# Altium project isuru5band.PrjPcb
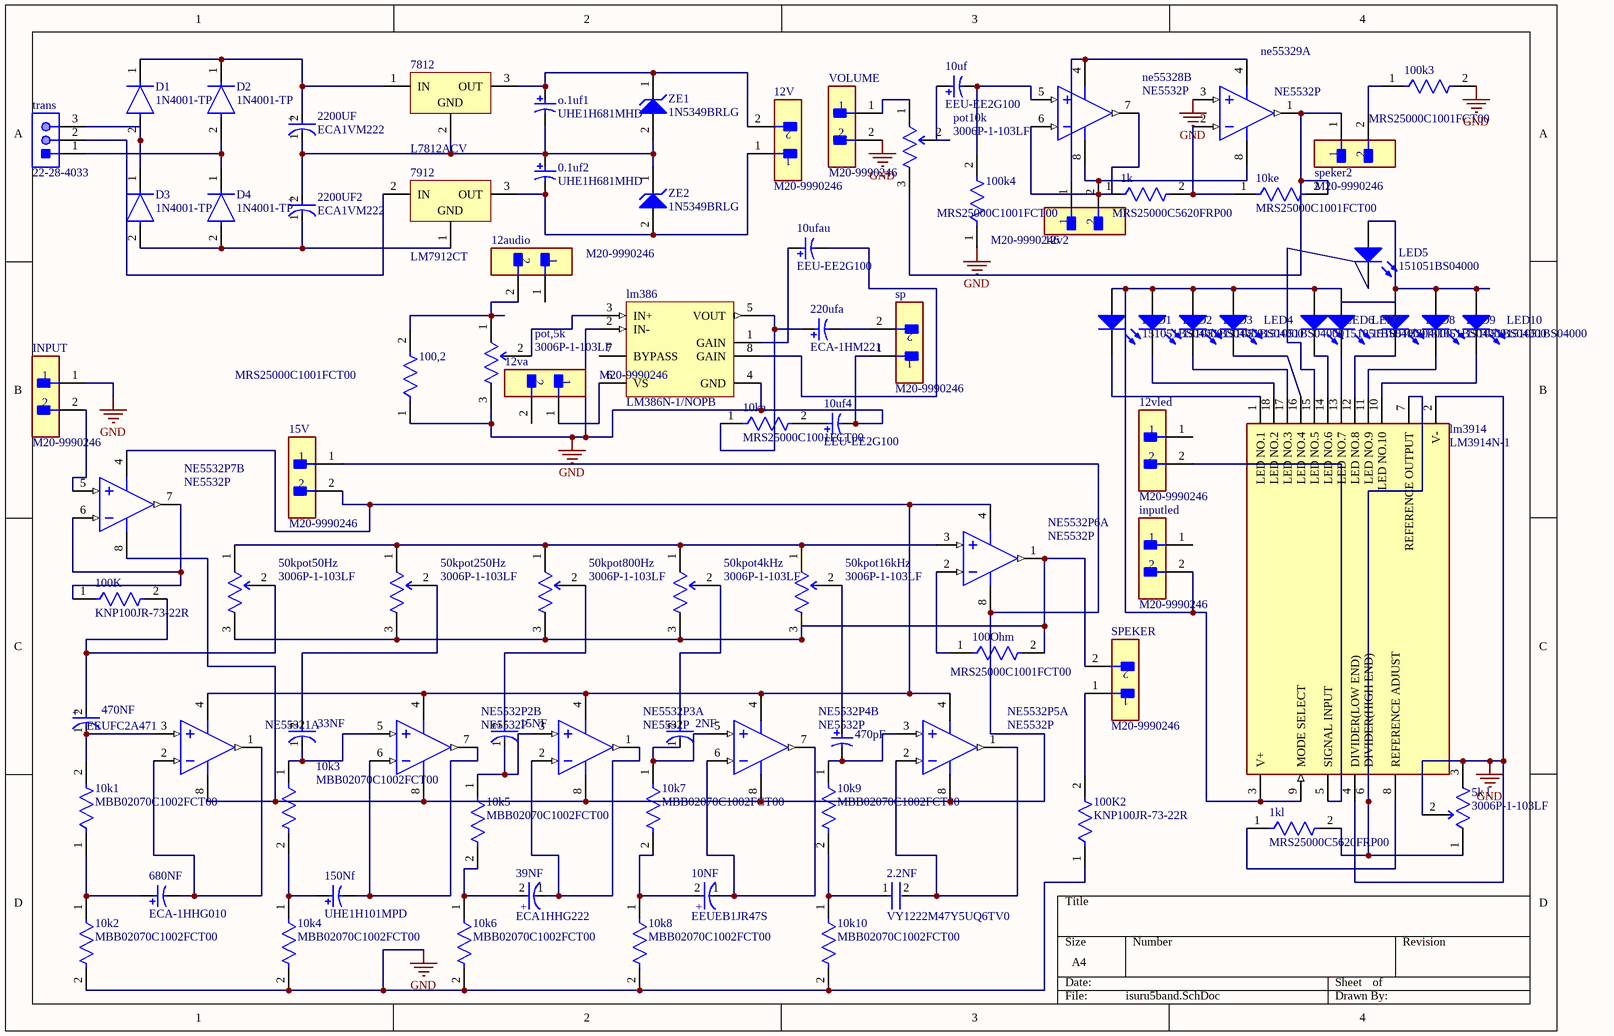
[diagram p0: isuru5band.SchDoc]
1 sheet, 88 parts. Net scope: global (net labels, ports and power ports of the same name join across sheets).
Board file: isuru5bandpcb.PcbDoc

## Sheet isuru5band.SchDoc
size A4; SheetNumber: 1; SheetTotal: 1

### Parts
0.1uf2  UHE1H681MHD  [NIC-UHE-12.5x31.5-2_V]
1k  MRS25000C5620FRP00  [FP-MRS25-MFG]
1kl  MRS25000C5620FRP00  [FP-MRS25-MFG]
2.2NF  VY1222M47Y5UQ6TV0  [FP-VY1470-MFG]
2NF  EEUHD1H561S  [FP-RAD-TH-D_16_0_5-L_15_1-MFG]  (value not drawn)
5k_l  3006P-1-103LF  [FP-3006P-MFG]
10k1  MBB02070C1002FCT00  [FP-MBB0207-MFG]
10k2  MBB02070C1002FCT00  [FP-MBB0207-MFG]
10k3  MBB02070C1002FCT00  [FP-MBB0207-MFG]
10k4  MBB02070C1002FCT00  [FP-MBB0207-MFG]
10k5  MBB02070C1002FCT00  [FP-MBB0207-MFG]
10k6  MBB02070C1002FCT00  [FP-MBB0207-MFG]
10k7  MBB02070C1002FCT00  [FP-MBB0207-MFG]
10k8  MBB02070C1002FCT00  [FP-MBB0207-MFG]
10k9  MBB02070C1002FCT00  [FP-MBB0207-MFG]
10k10  MBB02070C1002FCT00  [FP-MBB0207-MFG]
10ka  MRS25000C1001FCT00  [FP-MRS25-MFG]
10ke  MRS25000C1001FCT00  [FP-MRS25-MFG]
10NF  EEUEB1JR47S  [FP-RAD-TH-D_5_0_5-L_11_1-MFG]
10uf  EEU-EE2G100  [PNSC-EEU-EE2G100-2_V]
10uf4  EEU-EE2G100  [PNSC-EEU-EE2G100-2_V]
10ufau  EEU-EE2G100  [PNSC-EEU-EE2G100-2_V]
12audio  M20-9990246  [FP-M20-9990246-MFG]
12V  M20-9990246  [FP-M20-9990246-MFG]
12v2  M20-9990246  [FP-M20-9990246-MFG]
12va  M20-9990246  [FP-M20-9990246-MFG]
12vled  M20-9990246  [FP-M20-9990246-MFG]
15NF  EEUFR1H470  [FP-RAD-TH-D_6_3_0_5-L_11-MFG]  (value not drawn)
15V  M20-9990246  [FP-M20-9990246-MFG]
33NF  EEUFR1J271UB  [FP-RAD-TH-D_10_0_5-L_20_2-MFG]  (value not drawn)
39NF  ECA1HHG222  [FP-RAD-TH-D_16_0_5-L_31_5-MFG]
50kpot4kHz  3006P-1-103LF  [FP-3006P-MFG]
50kpot16kHz  3006P-1-103LF  [FP-3006P-MFG]
50kpot50Hz  3006P-1-103LF  [FP-3006P-MFG]
50kpot250Hz  3006P-1-103LF  [FP-3006P-MFG]
50kpot800Hz  3006P-1-103LF  [FP-3006P-MFG]
100,2  MRS25000C1001FCT00  [FP-MRS25-MFG]
100K  KNP100JR-73-22R  [FP-KNP100-MFG]
100K2  KNP100JR-73-22R  [FP-KNP100-MFG]
100k3  MRS25000C1001FCT00  [FP-MRS25-MFG]
100k4  MRS25000C1001FCT00  [FP-MRS25-MFG]
100Ohm  MRS25000C1001FCT00  [FP-MRS25-MFG]
150Nf  UHE1H101MPD  [NIC-UHE1H101MPD]
220ufa  ECA-1HM221  [CAPPR65-500-1250X1000X1350]
470NF  EEUFC2A471  [FP-RAD-TH-D_16_0_5-L_40_2-MFG]
470pF  ECA1HM4R7  [CAPPR55-200-1100X500X1200]  (value not drawn)
680NF  ECA-1HHG010  [CAPPR55-200-1100X500X1200]
2200UF  ECA1VM222  [FP-RAD-TH-D_16_0_5-L_25_2-MFG]
2200UF2  ECA1VM222  [FP-RAD-TH-D_16_0_5-L_25_2-MFG]
7812  L7812ACV  [TO220]
7912  LM7912CT  [NDE0003A]
D1  1N4001-TP  [FP-DO-41-MFG]
D2  1N4001-TP  [FP-DO-41-MFG]
D3  1N4001-TP  [FP-DO-41-MFG]
D4  1N4001-TP  [FP-DO-41-MFG]
INPUT  M20-9990246  [FP-M20-9990246-MFG]
inputled  M20-9990246  [FP-M20-9990246-MFG]
LED1  151051BS04000  [Type 5mm]
LED2  151051BS04000  [Type 5mm]
LED3  151051BS04000  [Type 5mm]
LED4  151051BS04000  [Type 5mm]
LED5  151051BS04000  [Type 5mm]
LED6  151051BS04000  [Type 5mm]
LED7  151051BS04000  [Type 5mm]
LED8  151051BS04000  [Type 5mm]
LED9  151051BS04000  [Type 5mm]
LED10  151051BS04000  [Type 5mm]
lm386  LM386N-1/NOPB  [P0008A]
lm3914  LM3914N-1  [FP-NFK0018A-MFG]
NE5532P2  NE5532P  [P0008A]  (part B of 2)
NE5532P3  NE5532P  [P0008A]  (part A of 2)
NE5532P4  NE5532P  [P0008A]  (part B of 2)
NE5532P5  NE5532P  [P0008A]  (part A of 2)
NE5532P6  NE5532P  [P0008A]  (part A of 2)
NE5532P7  NE5532P  [P0008A]  (part B of 2)
NE55321  NE5532P  [P0008A]  (value not drawn)  (part A of 2)
ne55328  NE5532P  [P0008A]  (part B of 2)
ne55329  NE5532P  [P0008A]  (part A of 2)
o.1uf1  UHE1H681MHD  [NIC-UHE-12.5x31.5-2_V]
pot10k  3006P-1-103LF  [FP-3006P-MFG]
pot,5k  3006P-1-103LF  [FP-3006P-MFG]
sp  M20-9990246  [FP-M20-9990246-MFG]
SPEKER  M20-9990246  [FP-M20-9990246-MFG]
speker2  M20-9990246  [FP-M20-9990246-MFG]
trans  22-28-4033  [MOLX-22-28-4033_V]
VOLUME  M20-9990246  [FP-M20-9990246-MFG]
ZE1  1N5349BRLG  [ONSC-SURMETIC40-2-017AA-01]
ZE2  1N5349BRLG  [ONSC-SURMETIC40-2-017AA-01]

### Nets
GND: 5k_l.2(WIPER) 5k_l.3(CW) 10k2.2 10k4.2 10k6.2 10k8.2 10k10.2 10uf4.2 100,2.1 100K2.1 100k3.2 100k4.1 INPUT.1 lm386.2(IN-) lm386.4(GND) lm3914.2(V-) lm3914.4(DIVIDER(LOW_END)) ne55329.3(IN1+) pot,5k.3(CW) sp.1 VOLUME.2
Net0.1uf2_1: 0.1uf2.1 2200UF.1(C) 2200UF2.2(A) 7812.2(GND) o.1uf1.2 ZE1.2(A) ZE2.1(K)
Net0.1uf2_2: 0.1uf2.2 12V.1 7912.3(OUT) ZE2.2(A)
Net1k_1: 1k.1 ne55328.6(IN2-) ne55328.7(OUT2)
Net1k_2: 1k.2 10ke.1 ne55329.2(IN1-)
Net1kl_1: 1kl.1 lm3914.8(REFERENCE_ADJUST)
Net1kl_2: 1kl.2 5k_l.1(CCW) lm3914.6(DIVIDER(HIGH_END)) lm3914.7(REFERENCE_OUTPUT)
Net2.2NF_1: 2.2NF.1 10k9.2 10k10.1
Net2.2NF_2: 2.2NF.2 NE5532P5.1(OUT1) NE5532P5.2(IN1-)
Net2NF_1: 2NF.1(C) 10k7.1 NE5532P4.5(IN2+)
Net2NF_2: 2NF.2(A) 50kpot4kHz.2(WIPER)
Net10k1_1: 10k1.1 10k2.1 680NF.1
Net10k1_2: 10k1.2 470NF.1(C) NE55321.3(IN1+)
Net10k3_1: 10k3.1 33NF.1(C) NE5532P2.5(IN2+)
Net10k3_2: 10k3.2 10k4.1 150Nf.1
Net10k5_1: 10k5.1 15NF.1(C) NE5532P3.3(IN1+)
Net10k5_2: 10k5.2 10k6.1 39NF.2(A)
Net10k7_2: 10k7.2 10k8.1 10NF.2(A)
Net10k9_1: 10k9.1 470pF.2 NE5532P5.3(IN1+)
Net10ka_1: 10ka.1 220ufa.1 lm386.5(VOUT)
Net10ka_2: 10ka.2 10uf4.1
Net10ke_2: 10ke.2 ne55329.1(OUT1) pot10k.3(CW) speker2.1
Net10NF_1: 10NF.1(C) NE5532P4.6(IN2-) NE5532P4.7(OUT2)
Net10uf_1: 10uf.1 pot10k.2(WIPER)
Net10uf_2: 10uf.2 100k4.2 ne55328.5(IN2+)
Net10ufau_1: 10ufau.1 lm386.1(GAIN)
Net10ufau_2: 10ufau.2 lm386.8(GAIN)
Net12audio_2: 12audio.2 100,2.2 pot,5k.1(CCW)
Net12v2_1: 12v2.1 ne55328.4(VCC-) ne55329.4(VCC-)
Net12v2_2: 12v2.2 ne55328.8(VCC+) ne55329.8(VCC+)
Net12V_2: 12V.2 7812.3(OUT) o.1uf1.1 ZE1.1(K)
Net12va_1: 12va.1 lm386.6(VS)
Net12vled_2: 12vled.2 lm3914.5(SIGNAL_INPUT)
Net15NF_2: 15NF.2(A) 50kpot800Hz.2(WIPER)
Net15V_1: 15V.1 NE5532P2.8(VCC+) NE5532P3.8(VCC+) NE5532P4.8(VCC+) NE5532P5.8(VCC+) NE5532P6.8(VCC+) NE5532P7.8(VCC+) NE55321.8(VCC+)
Net15V_2: 15V.2 NE5532P2.4(VCC-) NE5532P3.4(VCC-) NE5532P4.4(VCC-) NE5532P5.4(VCC-) NE5532P6.4(VCC-) NE5532P7.4(VCC-) NE55321.4(VCC-)
Net33NF_2: 33NF.2(A) 50kpot250Hz.2(WIPER)
Net39NF_1: 39NF.1(C) NE5532P3.1(OUT1) NE5532P3.2(IN1-)
Net50kpot4kHz_1: 50kpot4kHz.1(CCW) 50kpot16kHz.1(CCW) 50kpot50Hz.1(CCW) 50kpot250Hz.1(CCW) 50kpot800Hz.1(CCW) NE5532P6.3(IN1+)
Net50kpot4kHz_3: 50kpot4kHz.3(CW) 50kpot16kHz.3(CW) 50kpot50Hz.3(CW) 50kpot250Hz.3(CW) 50kpot800Hz.3(CW) 100Ohm.2 NE5532P6.1(OUT1) SPEKER.2
Net50kpot16kHz_2: 50kpot16kHz.2(WIPER) 470pF.1
Net50kpot50Hz_2: 50kpot50Hz.2(WIPER) 100K.2 470NF.2(A)
Net100K2_2: 100K2.2 SPEKER.1
Net100k3_1: 100k3.1 speker2.2
Net100K_1: 100K.1 NE5532P7.6(IN2-) NE5532P7.7(OUT2)
Net100Ohm_1: 100Ohm.1 NE5532P6.2(IN1-)
Net150Nf_2: 150Nf.2 NE5532P2.6(IN2-) NE5532P2.7(OUT2)
Net220ufa_2: 220ufa.2 sp.2
Net680NF_2: 680NF.2 NE55321.1(OUT1) NE55321.2(IN1-)
Net2200UF2_1: 2200UF2.1(C) 7912.1(GND) D3.2(A) D4.2(A)
Net2200UF_2: 2200UF.2(A) 7812.1(IN) D1.1(C) D2.1(C)
Net7912_2: 7912.2(IN) trans.2
NetD1_2: D1.2(A) D3.1(C) trans.3
NetD2_2: D2.2(A) D4.1(C) trans.1
NetINPUT_2: INPUT.2 NE5532P7.5(IN2+)
Netinputled_2: inputled.2 LED1.2(A) LED2.2(A) LED3.2(A) LED4.2(A) LED6.2(A) LED7.2(A) lm3914.3(V+) lm3914.9(MODE_SELECT)
NetLED1_1: LED1.1(K) lm3914.1(LED_NO.1)
NetLED2_1: LED2.1(K) lm3914.18(LED_NO.2)
NetLED3_1: LED3.1(K) lm3914.17(LED_NO.3)
NetLED4_1: LED4.1(K) lm3914.16(LED_NO.4)
NetLED5_1: LED5.1(K) lm3914.15(LED_NO.5)
NetLED5_2: LED5.2(A) LED8.2(A) LED9.2(A) LED10.2(A)
NetLED6_1: LED6.1(K) lm3914.14(LED_NO.6)
NetLED7_1: LED7.1(K) lm3914.13(LED_NO.7)
NetLED8_1: LED8.1(K) lm3914.12(LED_NO.8)
NetLED9_1: LED9.1(K) lm3914.11(LED_NO.9)
NetLED10_1: LED10.1(K) lm3914.10(LED_NO.10)
Netlm386_3: lm386.3(IN+) pot,5k.2(WIPER)
Netpot10k_1: pot10k.1(CCW) VOLUME.1

Not connected (* = marked no-connect by the designer): 12audio 1; 12va 2; 12vled 1; inputled 1; lm386 7(BYPASS)

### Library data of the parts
0.1uf2 o.1uf1 = CMP-1253-00001-1: Aluminum Electrolytic Capacitor, 680 uF +/-20%, 50 V, -40 to 105 degC, 2-Pin THD, RoHS, Bulk; Manufacturer: Nichicon; Rated Ripple: 2310 mA; Rated Capacitance: 680 uF; Rated Voltage: 50 V
1k 1kl = CMP-02408-000052-1: RES 562 OHM 0.6W 1% AXIAL; Lead Diameter: 0.6mm; Max Power Dissipation: 600mW; Voltage Rating: 350V; Resistance: 562R; Temperature Coefficient: 50ppm/°C
2.2NF = CMP-02417-000069-1: CAP CER 2200PF 760VAC Y5U RADIAL; Capacitance: 2.2nF; Lead Diameter: 0.6mm; Ratings: X1; Voltage Rating (AC): 500V; Lead/Base Style: Kinked; Tolerance: 20%
2NF = CMP-05427-001618-1: Aluminum Electrolytic Capacitors (Radial Lead Type) AEC-Q200 Qualified 560uF ±20% 50V; Ripple Current (AC): 650mA; Lead Diameter: 0.8mm; Life (Hours): 2000Hour; Lead/Base Style: Straight
5k_l 50kpot4kHz 50kpot16kHz 50kpot50Hz 50kpot250Hz 50kpot800Hz pot10k pot,5k = CMP-07234-000047-1: TRIMMER 10KOHM 0.75W PC PIN SIDE; Manufacturer Series: 3006; Pin Diameter: 0.6mm; Resistance Tolerance: 10%; Actuator Type: SCREW; Number of Turns: 15; Insulation Resistance: 1GR; Pitch: 2.5mm; Power Rating: 750mW; Resistance Law: Linear; Temperature Coefficient: 100ppm/°C; Resistance: 10kR; Number of Terminals/Pins: 3; Actuator Orientation: Horizontal
10k1-10k10 = CMP-02408-000035-1: RES 10K OHM 0.6W 1% AXIAL; Voltage Rating: 300V; Resistance: 10kR; Max Power Dissipation: 600mW; Temperature Coefficient: 50ppm/°C
10ka 10ke 100,2 100k3 100k4 100Ohm = CMP-02408-000051-1: RES 1K OHM 0.6W 1% AXIAL; Power Rating: 600mW; Lead Diameter: 0.6mm; Voltage Rating (DC): 350V; Resistance: 1kR; Temperature Coefficient: 50ppm/°C
10NF = CMP-05427-001047-1: Aluminum Electrolytic Capacitors (Radial Lead Type) 0.47uF ±20% 63V; Life (Hours): 5000Hour; Ripple Current: 4.5mA; Lead Diameter: 0.5mm; Leakage Current: 3uA; Capacitance: 470nF; Polarity: Polar
10uf 10uf4 10ufau = CMP-0736-00002-1: Aluminum Electrolytic Capacitor, 10 uF +/- 20%, 400 V, -25 to 105 degC, 2-Pin 10 x 10 x 22 mm Through-hole, RoHS, Tape and Reel; Manufacturer: Panasonic; Ripple Current: 430 mA; Rated Voltage: 400 V; Cap.: 10 uF; Capacitance Tolerance: +/- 20%
12audio 12V 12v2 12va 12vled 15V INPUT inputled sp SPEKER speker2 VOLUME = CMP-15831-000009-1: CONN HEADER VERT 2POS 2.54MM; Manufacturer: Harwin; Conn Gender: Male; Conn Orientation: Vertical; Number Of Contacts: 2; Current Rating: 3A
15NF = CMP-05427-001321-1: Aluminum Electrolytic Capacitors (Radial Lead Type) 47uF ±20% 50V; Lead Diameter: 0.5mm; Ripple Current (AC): 405mA; Impedance: 140mR; Life (Hours): 5000Hour
33NF = CMP-05427-000491-1: Aluminum Electrolytic Capacitors (Radial Lead Type) 270uF ±20% 63V; Impedance: 35mR; Ripple Current: 1.229A; Lead Diameter: 0.6mm; Life (Hours): 10000Hour
39NF = CMP-05427-001651-1: Aluminum Electrolytic Capacitors (Radial Lead Type) AEC-Q200 Qualified 2200uF ±20% 50V; Leakage Current: 3uA; Ripple Current (AC): 1.47A; Capacitance: 2.2mF; Lead Diameter: 0.8mm; Lead/Base Style: Straight; Dissipation Factor: 0.14%; Life (Hours): 2000Hour
100K 100K2 = CMP-03413-000004-1: RES 22 OHM 1W 5% AXIAL; Manufacturer: Yageo; Value: 22Ω; Temperature Coefficient: 300ppm/°C
150Nf = CMP-2000-07349-1: Aluminium Electrolytic Capacitor, 100 uF, +/- 20%, 50 V, -40 to 105 degC, 2-Pin THD, RoHS, Bulk; Manufacturer: Nichicon; Rated Voltage: 50V; Capacitance: 100µF
220ufa = CMP-1665-00043-1: Aluminum Electrolytic Capacitor, 220 uF, +/- 20%, 50 V, -40 to 85 degC, 2-Pin THD, RoHS, Bulk; Max Supply Voltage: 5.5 V; Min Supply Voltage: 4.5 V; Propagation Delay: 10 us; Data Rate: 120 kbps; Nominal Supply Current: 10 mA; Case\Package: SOIC; Nominal Supply Voltage: 5 V; Channels: 2; Interface: RS-232
470NF = CMP-05427-000270-1: Aluminum Electrolytic Capacitors (Radial Lead Type) AEC-Q200 Qualified 470uF ±20% 100V; Ripple Current: 1.92A; Impedance: 47mR; Polarity: Polar; Dielectric Material: Aluminium; Lead Diameter: 0.8mm; Life (Hours): 5000Hour; Leakage Current: 3uA
470pF = CMP-1665-00037-2: Aluminum Electrolytic Capacitor, 4.7 uF, +/- 20%, 50 V, -40 to 85 degC, 2-Pin THD, RoHS, Bulk; Manufacturer: Panasonic; Life (Hours): 2000Hour; Dielectric Material: Aluminium; Voltage Rating: 50V; Leakage Current: 3uA; Ripple Current: 45mA; Capacitance: 4.7uF; Lead/Base Style: Straight; Dissipation Factor: 0.12%; Lead Diameter: 0.5mm
680NF = CMP-1665-00039-1: Aluminum Electrolytic Capacitor, 1 uF, +/- 20%, 50 V, -55 to 105 degC, 2-Pin THD, RoHS, Bulk; Channels: 2
2200UF 2200UF2 = CMP-05427-001795-1: Aluminum Electrolytic Capacitors (Radial Lead Type) 2200uF ±20% 35V; Capacitance: 2.2mF; Leakage Current: 3uA; Lead Diameter: 0.8mm; Ripple Current: 1.25A; Life (Hours): 2000Hour; Lead/Base Style: Straight
7812 = CMP-0244-00451-1: Positive Voltage Regulator, 12V, 3-Pin TO-220
7912 = CMP-0062-02472-3: 3-Terminal Negative Regulator, 3-pin TO-220; Manufacturer: Texas Instruments; CompType: LDO IC; PowerWise: N; PackageTopMarking: NSUZXYTTE#*LM7912CT
D1-D4 = CMP-56207-000001-1: DIODE GEN PURP 50V 1A DO41; Manufacturer: Micro Commercial; Max Surge Forward Current: 30A; Max Junction Temp: +150°C; Capacitance: 15pF; Peak Reverse Current: 5uA; Value: 15pF
LED1-LED10 = CMP-1488-00009-1: THT LED round mono-color color lens, WL-TMRW, Blue; Manufacturer: Wuerth Elektronik
lm386 = CMP-0057-00052-4: Low Voltage Audio Power Amplifier, 8-pin MDIP, Pb-Free; Manufacturer: Texas Instruments; PackageTopMarking: NSUZXYTTE#*LM*386N-1; PowerWise: N; CompType: Audio IC
lm3914 = CMP-0058-00006-4: IC DRVR DOT/BAR DISPLAY 18DIP; Output Current: 30mA; Supply Current: 9.2mA; Output Voltage: 1.28V; Number of Outputs: 10; Max Output Voltage: 1.34V; Power Dissipation: 1.365W; Operating Supply Current: 6.1mA; Max Input Voltage: 12V; Max Supply Current: 9.2kA; Min Input Voltage: 1.2V; Max Supply Voltage: 25V
NE5532P2-NE5532P7 NE55321 ne55328 ne55329 = CMP-0017-00910-2: Dual Low-Noise High-Speed Audio Operational Amplifier, 10 to 30 V, 0 to 70 degC, 8-pin DIP (P8), Pb-Free (RoHS); Manufacturer: Texas Instruments; Iq per channel(Max)(mA): 4; Slew Rate(Typ)(V/us): 9; Vn at 1kHz(Typ)(nV/rtHz): 5; IIB(Max)(pA): 800000; Total Supply Voltage(Max)(+5V is 5, +/-5V is 10): 30; GBW(Typ)(MHz): 10; CMRR(Min)(dB): 70; Number of Channels: 2; Sub Family: General Purpose Amplifier, High Supply Voltage Amplifier (>=30V), Low Noise Amp (<=10nV/rtHz)
trans = CMP-1676-00001-5: Male Header, Pitch 2.54 mm, 1 x 3 Position, Height 8.38 mm, Tail Length 3.18 mm, RoHS, Bulk; Manufacturer: Molex; Rows: 1; Voltage Rating: 250 V; Current Rating: 4 A
ZE1 ZE2 = CMP-1060-01279-1: 5 W Zener Voltage Regulator, 2-Pin Surmetic(TM) 40, Pb-Free, Tape and Reel; Manufacturer: On Semiconductor; P Max (W): 5; VZ Typ (V): 12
